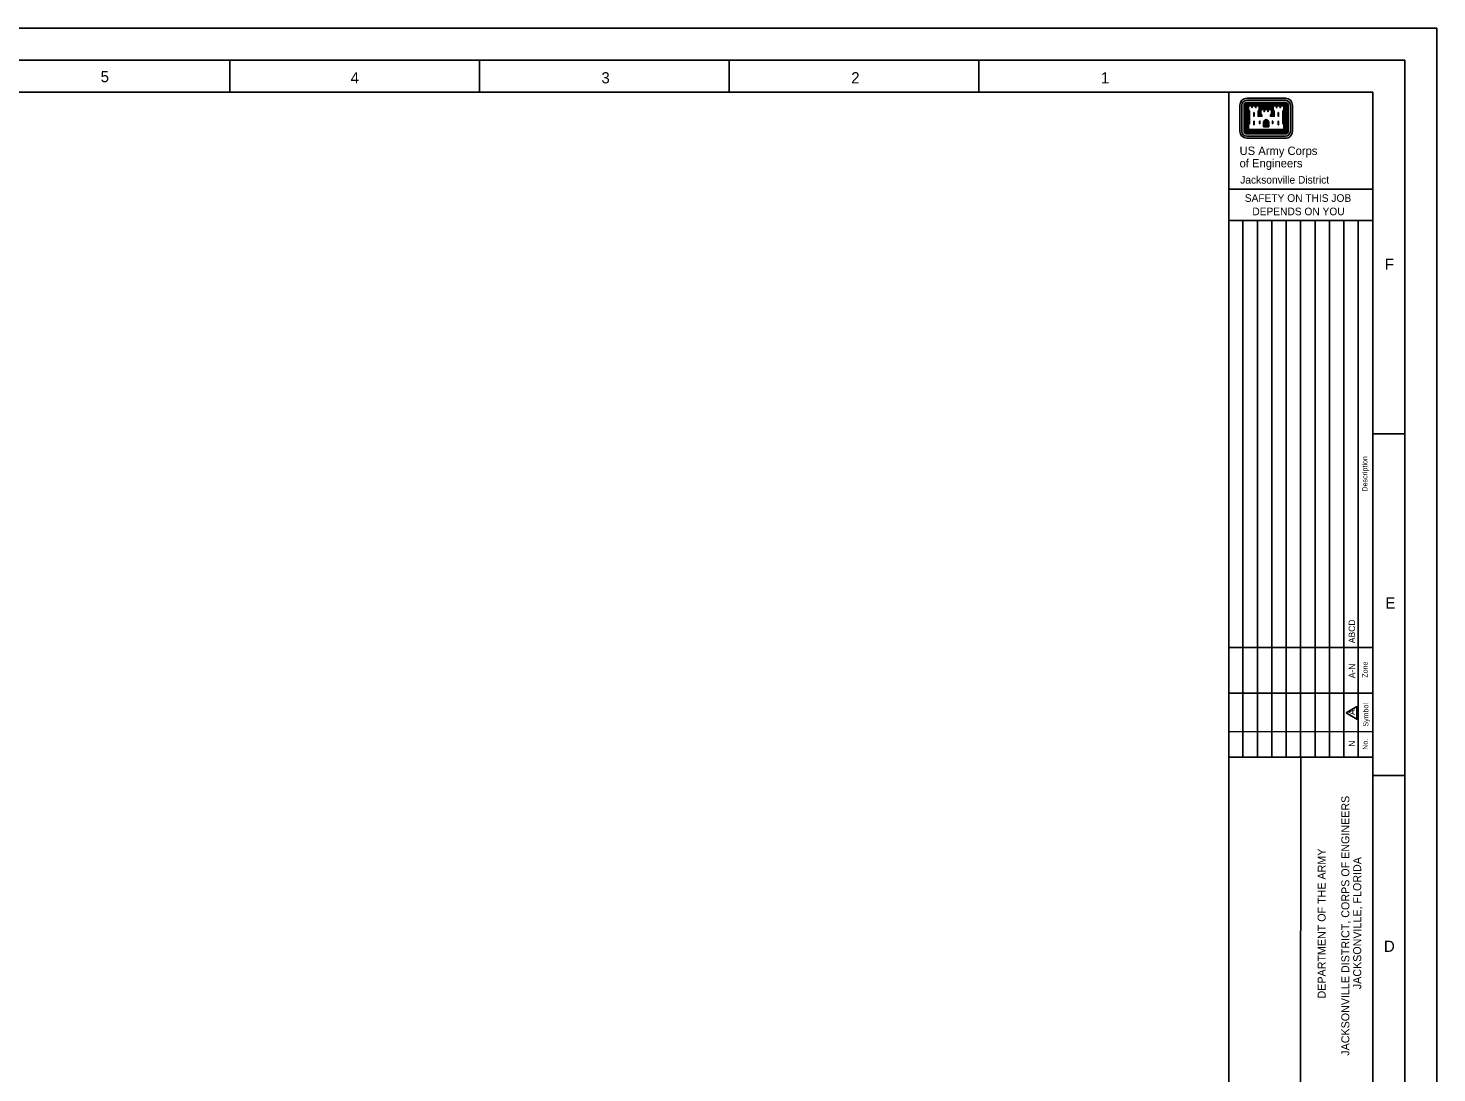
# Model space of a CAD drawing. Extents: x 1945213.1 to 1945257.1, y 2038820.4 to 2038854.4.
# Drawn here: x 1945235.14 to 1945257.14, y 2038838.07 to 2038854.38 of the extents above; entities that cross this region are included whole.
import ezdxf

# ---------------------------------------------------------------- set-up
doc = ezdxf.new("R2010")
doc.units = 0
for name, color, linetype in [('G-ANNO-NPLT', 7, 'Continuous'), ('G-ANNO-SYMB', 7, 'Continuous'), ('G-ANNO-TEXT-DRWG', 7, 'Continuous'), ('G-ANNO-TEXT-TTLB', 7, 'Continuous'), ('G-ANNO-TTLB', 7, 'Continuous')]:
    doc.layers.add(name, color=color, linetype=linetype)

msp = doc.modelspace()

# ---------------------------------------------------------------- linework, layer by layer
at = {"layer": 'G-ANNO-NPLT'}
msp.add_lwpolyline([(1945213.137, 2038854.377), (1945257.137, 2038854.377), (1945257.137, 2038820.377), (1945213.137, 2038820.377)], close=True, dxfattribs=at)
msp.add_lwpolyline([(1945257.137, 2038853.877), (1945257.137, 2038854.377), (1945256.637, 2038854.377)], dxfattribs=at)
at = {"layer": 'G-ANNO-SYMB'}
for p, q in [((1945254.776, 2038853.283), (1945254.168, 2038853.283)), ((1945254.061, 2038853.176), (1945254.061, 2038852.766)), ((1945254.093, 2038852.766), (1945254.093, 2038853.176)), ((1945254.128, 2038853.176), (1945254.128, 2038852.766)), ((1945254.137, 2038853.176), (1945254.137, 2038852.766)), ((1945254.145, 2038853.176), (1945254.145, 2038852.766)), ((1945254.154, 2038853.176), (1945254.154, 2038852.766)), ((1945254.163, 2038853.176), (1945254.163, 2038852.766)), ((1945254.168, 2038853.251), (1945254.776, 2038853.251)), ((1945254.776, 2038853.217), (1945254.168, 2038853.217)), ((1945254.776, 2038853.208), (1945254.168, 2038853.208)), ((1945254.776, 2038853.199), (1945254.168, 2038853.199)), ((1945254.776, 2038853.191), (1945254.168, 2038853.191)), ((1945254.776, 2038853.182), (1945254.168, 2038853.182)), ((1945254.172, 2038853.176), (1945254.172, 2038852.769)), ((1945254.18, 2038853.176), (1945254.18, 2038852.778)), ((1945254.187, 2038853.089), (1945254.187, 2038852.879)), ((1945254.196, 2038853.08), (1945254.196, 2038852.889)), ((1945254.379, 2038853.174), (1945254.565, 2038853.174)), ((1945254.379, 2038853.165), (1945254.565, 2038853.165)), ((1945254.379, 2038853.157), (1945254.565, 2038853.157)), ((1945254.379, 2038853.148), (1945254.565, 2038853.148)), ((1945254.379, 2038853.139), (1945254.565, 2038853.139)), ((1945254.379, 2038853.131), (1945254.565, 2038853.131)), ((1945254.379, 2038853.122), (1945254.565, 2038853.122)), ((1945254.748, 2038853.08), (1945254.748, 2038852.889)), ((1945254.757, 2038853.088), (1945254.757, 2038852.88)), ((1945254.764, 2038853.176), (1945254.764, 2038852.778)), ((1945254.772, 2038853.176), (1945254.772, 2038852.769)), ((1945254.781, 2038853.176), (1945254.781, 2038852.766)), ((1945254.79, 2038853.176), (1945254.79, 2038852.766)), ((1945254.798, 2038853.176), (1945254.798, 2038852.766)), ((1945254.807, 2038853.176), (1945254.807, 2038852.766)), ((1945254.816, 2038853.176), (1945254.816, 2038852.766)), ((1945254.85, 2038853.176), (1945254.85, 2038852.766)), ((1945254.883, 2038852.766), (1945254.883, 2038853.176)), ((1945254.432, 2038852.837), (1945254.432, 2038852.904)), ((1945254.432, 2038852.837), (1945254.512, 2038852.837)), ((1945254.44, 2038852.837), (1945254.44, 2038852.904)), ((1945254.449, 2038852.837), (1945254.449, 2038852.904)), ((1945254.458, 2038852.837), (1945254.458, 2038852.904)), ((1945254.466, 2038852.837), (1945254.466, 2038852.904)), ((1945254.478, 2038852.837), (1945254.478, 2038852.904)), ((1945254.486, 2038852.837), (1945254.486, 2038852.904)), ((1945254.495, 2038852.837), (1945254.495, 2038852.904)), ((1945254.504, 2038852.837), (1945254.504, 2038852.904)), ((1945254.512, 2038852.837), (1945254.512, 2038852.904)), ((1945254.776, 2038852.76), (1945254.168, 2038852.76)), ((1945254.776, 2038852.752), (1945254.168, 2038852.752)), ((1945254.776, 2038852.743), (1945254.168, 2038852.743)), ((1945254.776, 2038852.734), (1945254.168, 2038852.734)), ((1945254.776, 2038852.726), (1945254.168, 2038852.726)), ((1945254.776, 2038852.691), (1945254.168, 2038852.691)), ((1945254.168, 2038852.658), (1945254.776, 2038852.658)), ((1945254.772, 2038852.769), (1945254.172, 2038852.769)), ((1945254.764, 2038852.778), (1945254.18, 2038852.778))]:
    msp.add_line(p, q, dxfattribs=at)
for points in [[(1945254.187, 2038853.176), (1945254.187, 2038853.097), (1945254.204, 2038853.08), (1945254.204, 2038852.889), (1945254.187, 2038852.871), (1945254.187, 2038852.784), (1945254.757, 2038852.784), (1945254.757, 2038852.871), (1945254.739, 2038852.889), (1945254.739, 2038853.08), (1945254.757, 2038853.097), (1945254.757, 2038853.176), (1945254.682, 2038853.176), (1945254.624, 2038853.176), (1945254.57, 2038853.176), (1945254.57, 2038853.097), (1945254.589, 2038853.08), (1945254.589, 2038853.01), (1945254.547, 2038853.01), (1945254.547, 2038853.017), (1945254.565, 2038853.035), (1945254.565, 2038853.113), (1945254.49, 2038853.113), (1945254.432, 2038853.113), (1945254.379, 2038853.113), (1945254.379, 2038853.035), (1945254.397, 2038853.017), (1945254.397, 2038853.01), (1945254.355, 2038853.01), (1945254.355, 2038853.08), (1945254.373, 2038853.097), (1945254.373, 2038853.176), (1945254.298, 2038853.176), (1945254.24, 2038853.176), (1945254.187, 2038853.176)], [(1945254.195, 2038853.167), (1945254.195, 2038853.101), (1945254.213, 2038853.083), (1945254.213, 2038852.885), (1945254.195, 2038852.867), (1945254.195, 2038852.793), (1945254.749, 2038852.793), (1945254.749, 2038852.867), (1945254.73, 2038852.885), (1945254.73, 2038853.083), (1945254.749, 2038853.101), (1945254.749, 2038853.167), (1945254.695, 2038853.167), (1945254.695, 2038853.136), (1945254.69, 2038853.136), (1945254.69, 2038853.167), (1945254.637, 2038853.167), (1945254.637, 2038853.136), (1945254.633, 2038853.136), (1945254.633, 2038853.167), (1945254.579, 2038853.167), (1945254.579, 2038853.101), (1945254.597, 2038853.083), (1945254.597, 2038853.002), (1945254.539, 2038853.002), (1945254.539, 2038853.021), (1945254.557, 2038853.039), (1945254.557, 2038853.105), (1945254.503, 2038853.105), (1945254.503, 2038853.074), (1945254.499, 2038853.074), (1945254.499, 2038853.105), (1945254.445, 2038853.105), (1945254.445, 2038853.074), (1945254.44, 2038853.074), (1945254.44, 2038853.105), (1945254.387, 2038853.105), (1945254.387, 2038853.039), (1945254.405, 2038853.021), (1945254.405, 2038853.002), (1945254.347, 2038853.002), (1945254.347, 2038853.083), (1945254.365, 2038853.101), (1945254.365, 2038853.167), (1945254.312, 2038853.167), (1945254.312, 2038853.136), (1945254.307, 2038853.136), (1945254.307, 2038853.167), (1945254.253, 2038853.167), (1945254.253, 2038853.136), (1945254.249, 2038853.136), (1945254.249, 2038853.167), (1945254.195, 2038853.167)], [(1945254.277, 2038853.06), (1945254.277, 2038853.002), (1945254.283, 2038853.002), (1945254.283, 2038853.06), (1945254.277, 2038853.06)], [(1945254.369, 2038853.081), (1945254.364, 2038853.076), (1945254.364, 2038853.019), (1945254.383, 2038853.019), (1945254.37, 2038853.032), (1945254.37, 2038853.082)], [(1945254.575, 2038853.081), (1945254.58, 2038853.076), (1945254.58, 2038853.019), (1945254.562, 2038853.019), (1945254.574, 2038853.032), (1945254.574, 2038853.082)], [(1945254.666, 2038853.06), (1945254.666, 2038853.002), (1945254.661, 2038853.002), (1945254.661, 2038853.06), (1945254.666, 2038853.06)], [(1945254.277, 2038852.927), (1945254.277, 2038852.868), (1945254.283, 2038852.868), (1945254.283, 2038852.927), (1945254.277, 2038852.927)], [(1945254.369, 2038852.927), (1945254.369, 2038852.886), (1945254.374, 2038852.886), (1945254.374, 2038852.927), (1945254.369, 2038852.927)], [(1945254.575, 2038852.927), (1945254.575, 2038852.886), (1945254.57, 2038852.886), (1945254.57, 2038852.927), (1945254.575, 2038852.927)], [(1945254.666, 2038852.927), (1945254.666, 2038852.868), (1945254.661, 2038852.868), (1945254.661, 2038852.927), (1945254.666, 2038852.927)]]:
    msp.add_lwpolyline(points, dxfattribs=at)
for centre, major_axis, start_param, end_param in [((1945254.168, 2038853.176), (0.107, 0), 1.57078, 3.141576), ((1945254.775, 2038853.176), (0.107, 0), 6.283169, 7.853965), ((1945254.168, 2038853.176), (0.0749, 0), 1.57078, 3.141576), ((1945254.168, 2038853.176), (0.0402, 0), 1.57078, 3.141576), ((1945254.168, 2038853.176), (0.0315, 0), 1.57078, 3.141576), ((1945254.168, 2038853.176), (0.0228, 0), 1.57078, 3.141576), ((1945254.168, 2038853.176), (0.0141, 0), 1.57078, 3.141576), ((1945254.168, 2038853.176), (0.00546, 0), 1.57078, 3.141576), ((1945254.775, 2038853.176), (0.0749, 0), 6.28317, 7.853966), ((1945254.775, 2038853.176), (0.0402, 0), 6.283169, 7.853965), ((1945254.775, 2038853.176), (0.0315, 0), 6.283169, 7.853965), ((1945254.775, 2038853.176), (0.0228, 0), 6.283169, 7.853965), ((1945254.775, 2038853.176), (0.0141, 0), 6.283169, 7.853965), ((1945254.775, 2038853.176), (0.00546, 0), 6.283169, 7.853965), ((1945254.487, 2038852.9), (-0.0555, 0), 4.985832, 6.214359), ((1945254.487, 2038852.9), (-0.0469, 0), 4.947465, 6.21436), ((1945254.487, 2038852.9), (-0.0382, 0), 4.947465, 6.21436), ((1945254.487, 2038852.9), (-0.0295, 0), 4.947465, 6.21436), ((1945254.457, 2038852.9), (0.0208, 0), 0.068794, 1.335689), ((1945254.457, 2038852.9), (0.0295, 0), 0.068794, 1.335689), ((1945254.457, 2038852.9), (0.0382, 0), 0.068795, 1.335689), ((1945254.487, 2038852.9), (-0.0208, 0), 4.947465, 6.214359), ((1945254.457, 2038852.9), (0.0469, 0), 0.068795, 1.335689), ((1945254.457, 2038852.9), (0.0555, 0), 0.068795, 1.29842), ((1945254.168, 2038852.766), (-0.107, 0), 6.28317, 7.853966), ((1945254.168, 2038852.766), (-0.0749, 0), 6.28317, 7.853966), ((1945254.168, 2038852.766), (-0.0402, 0), 6.28317, 7.853966), ((1945254.168, 2038852.766), (-0.0315, 0), 6.28317, 7.853966), ((1945254.168, 2038852.766), (-0.0228, 0), 6.28317, 7.853966), ((1945254.168, 2038852.766), (-0.0141, 0), 6.28317, 7.853966), ((1945254.168, 2038852.766), (-0.00546, 0), 6.28317, 7.853966), ((1945254.775, 2038852.766), (0.0402, 0), 4.712373, 6.28317), ((1945254.775, 2038852.766), (0.0315, 0), 4.712373, 6.28317), ((1945254.775, 2038852.766), (0.0228, 0), 4.712373, 6.28317), ((1945254.775, 2038852.766), (0.0141, 0), 4.712373, 6.28317), ((1945254.775, 2038852.766), (0.00546, 0), 4.712373, 6.28317), ((1945254.775, 2038852.766), (0.107, 0), 4.712373, 6.28317), ((1945254.775, 2038852.766), (-0.0749, 0), 1.570781, 3.141577)]:
    msp.add_ellipse(centre, major_axis=major_axis, ratio=0.99964, start_param=start_param, end_param=end_param, dxfattribs=at)
at = {"layer": 'G-ANNO-TEXT-DRWG'}
msp.add_lwpolyline([(1945255.719, 2038843.686), (1945255.89, 2038843.587), (1945255.89, 2038843.785), (1945255.719, 2038843.686)], dxfattribs=at)
at = {"layer": 'G-ANNO-TTLB'}
for p, q in [((1945238.287, 2038853.877), (1945238.287, 2038853.377)), ((1945242.187, 2038853.877), (1945242.187, 2038853.377)), ((1945246.087, 2038853.877), (1945246.087, 2038853.377)), ((1945249.987, 2038853.877), (1945249.987, 2038853.377)), ((1945253.887, 2038853.377), (1945253.887, 2038821.377)), ((1945253.887, 2038851.865), (1945256.137, 2038851.865)), ((1945253.881, 2038851.374), (1945256.131, 2038851.374)), ((1945254.11, 2038851.374), (1945254.11, 2038842.994)), ((1945254.335, 2038851.374), (1945254.335, 2038842.994)), ((1945254.56, 2038851.374), (1945254.56, 2038842.994)), ((1945254.785, 2038851.374), (1945254.785, 2038842.994)), ((1945255.01, 2038851.374), (1945255.01, 2038842.994)), ((1945255.235, 2038851.374), (1945255.235, 2038842.994)), ((1945255.46, 2038851.374), (1945255.46, 2038842.994)), ((1945255.685, 2038851.374), (1945255.685, 2038842.994)), ((1945255.91, 2038851.374), (1945255.91, 2038842.994)), ((1945256.637, 2038848.042), (1945256.137, 2038848.042)), ((1945253.887, 2038844.705), (1945256.137, 2038844.705)), ((1945253.887, 2038843.993), (1945256.137, 2038843.993)), ((1945253.887, 2038843.393), (1945256.137, 2038843.392)), ((1945253.887, 2038842.994), (1945256.137, 2038842.994)), ((1945255.006, 2038834.399), (1945255.012, 2038842.994)), ((1945255.012, 2038842.994), (1945255.012, 2038842.64)), ((1945256.637, 2038842.709), (1945256.137, 2038842.709))]:
    msp.add_line(p, q, dxfattribs=at)
for points in [[(1945213.637, 2038820.877), (1945256.637, 2038820.877), (1945256.637, 2038853.877), (1945213.637, 2038853.877)], [(1945256.137, 2038853.377), (1945214.887, 2038853.377), (1945214.887, 2038821.377), (1945256.137, 2038821.377)]]:
    msp.add_lwpolyline(points, close=True, dxfattribs=at)

# ---------------------------------------------------------------- texts
at = {"layer": 'G-ANNO-SYMB'}
for s, height, p in [('US Army Corps', 0.13086, (1945254.057, 2038852.397)), ('of Engineers', 0.13086, (1945254.057, 2038852.203)), ('Jacksonville District', 0.119, (1945254.067, 2038851.95)), ('SAFETY ON THIS JOB', 0.119, (1945254.138, 2038851.665)), ('DEPENDS ON YOU', 0.119, (1945254.256, 2038851.456))]:
    msp.add_text(s, height=height, rotation=360, dxfattribs=at).set_placement(p)
at = {"layer": 'G-ANNO-TEXT-DRWG'}
for s, p in [('ABCD', (1945255.86, 2038844.773)), ('A-N', (1945255.862, 2038844.226)), ('A', (1945255.86, 2038843.651)), ('N', (1945255.86, 2038843.156))]:
    msp.add_text(s, height=0.1, rotation=90, dxfattribs=at).set_placement(p)
at = {"layer": 'G-ANNO-TEXT-TTLB'}
for s, height, p in [('Description', 0.08, (1945256.053, 2038847.142)), ('Zone', 0.08, (1945256.056, 2038844.235)), ('Symbol', 0.08, (1945256.068, 2038843.471)), ('No.', 0.08, (1945256.058, 2038843.11)), ('JACKSONVILLE DISTRICT, CORPS OF ENGINEERS', 0.125, (1945255.771, 2038838.332)), ('DEPARTMENT OF THE ARMY', 0.125, (1945255.401, 2038839.226)), ('JACKSONVILLE, FLORIDA', 0.125, (1945255.956, 2038839.371))]:
    msp.add_text(s, height=height, rotation=90, dxfattribs=at).set_placement(p)
at = {"layer": 'G-ANNO-TTLB'}
for s, p in [('5', (1945236.27, 2038853.534)), ('4', (1945240.174, 2038853.515)), ('3', (1945244.091, 2038853.515)), ('2', (1945247.992, 2038853.515)), ('1', (1945251.891, 2038853.515)), ('F', (1945256.325, 2038850.604)), ('E', (1945256.333, 2038845.315)), ('D', (1945256.311, 2038839.954))]:
    msp.add_text(s, height=0.175, rotation=360, dxfattribs=at).set_placement(p)

doc.saveas('drawing.dxf')
